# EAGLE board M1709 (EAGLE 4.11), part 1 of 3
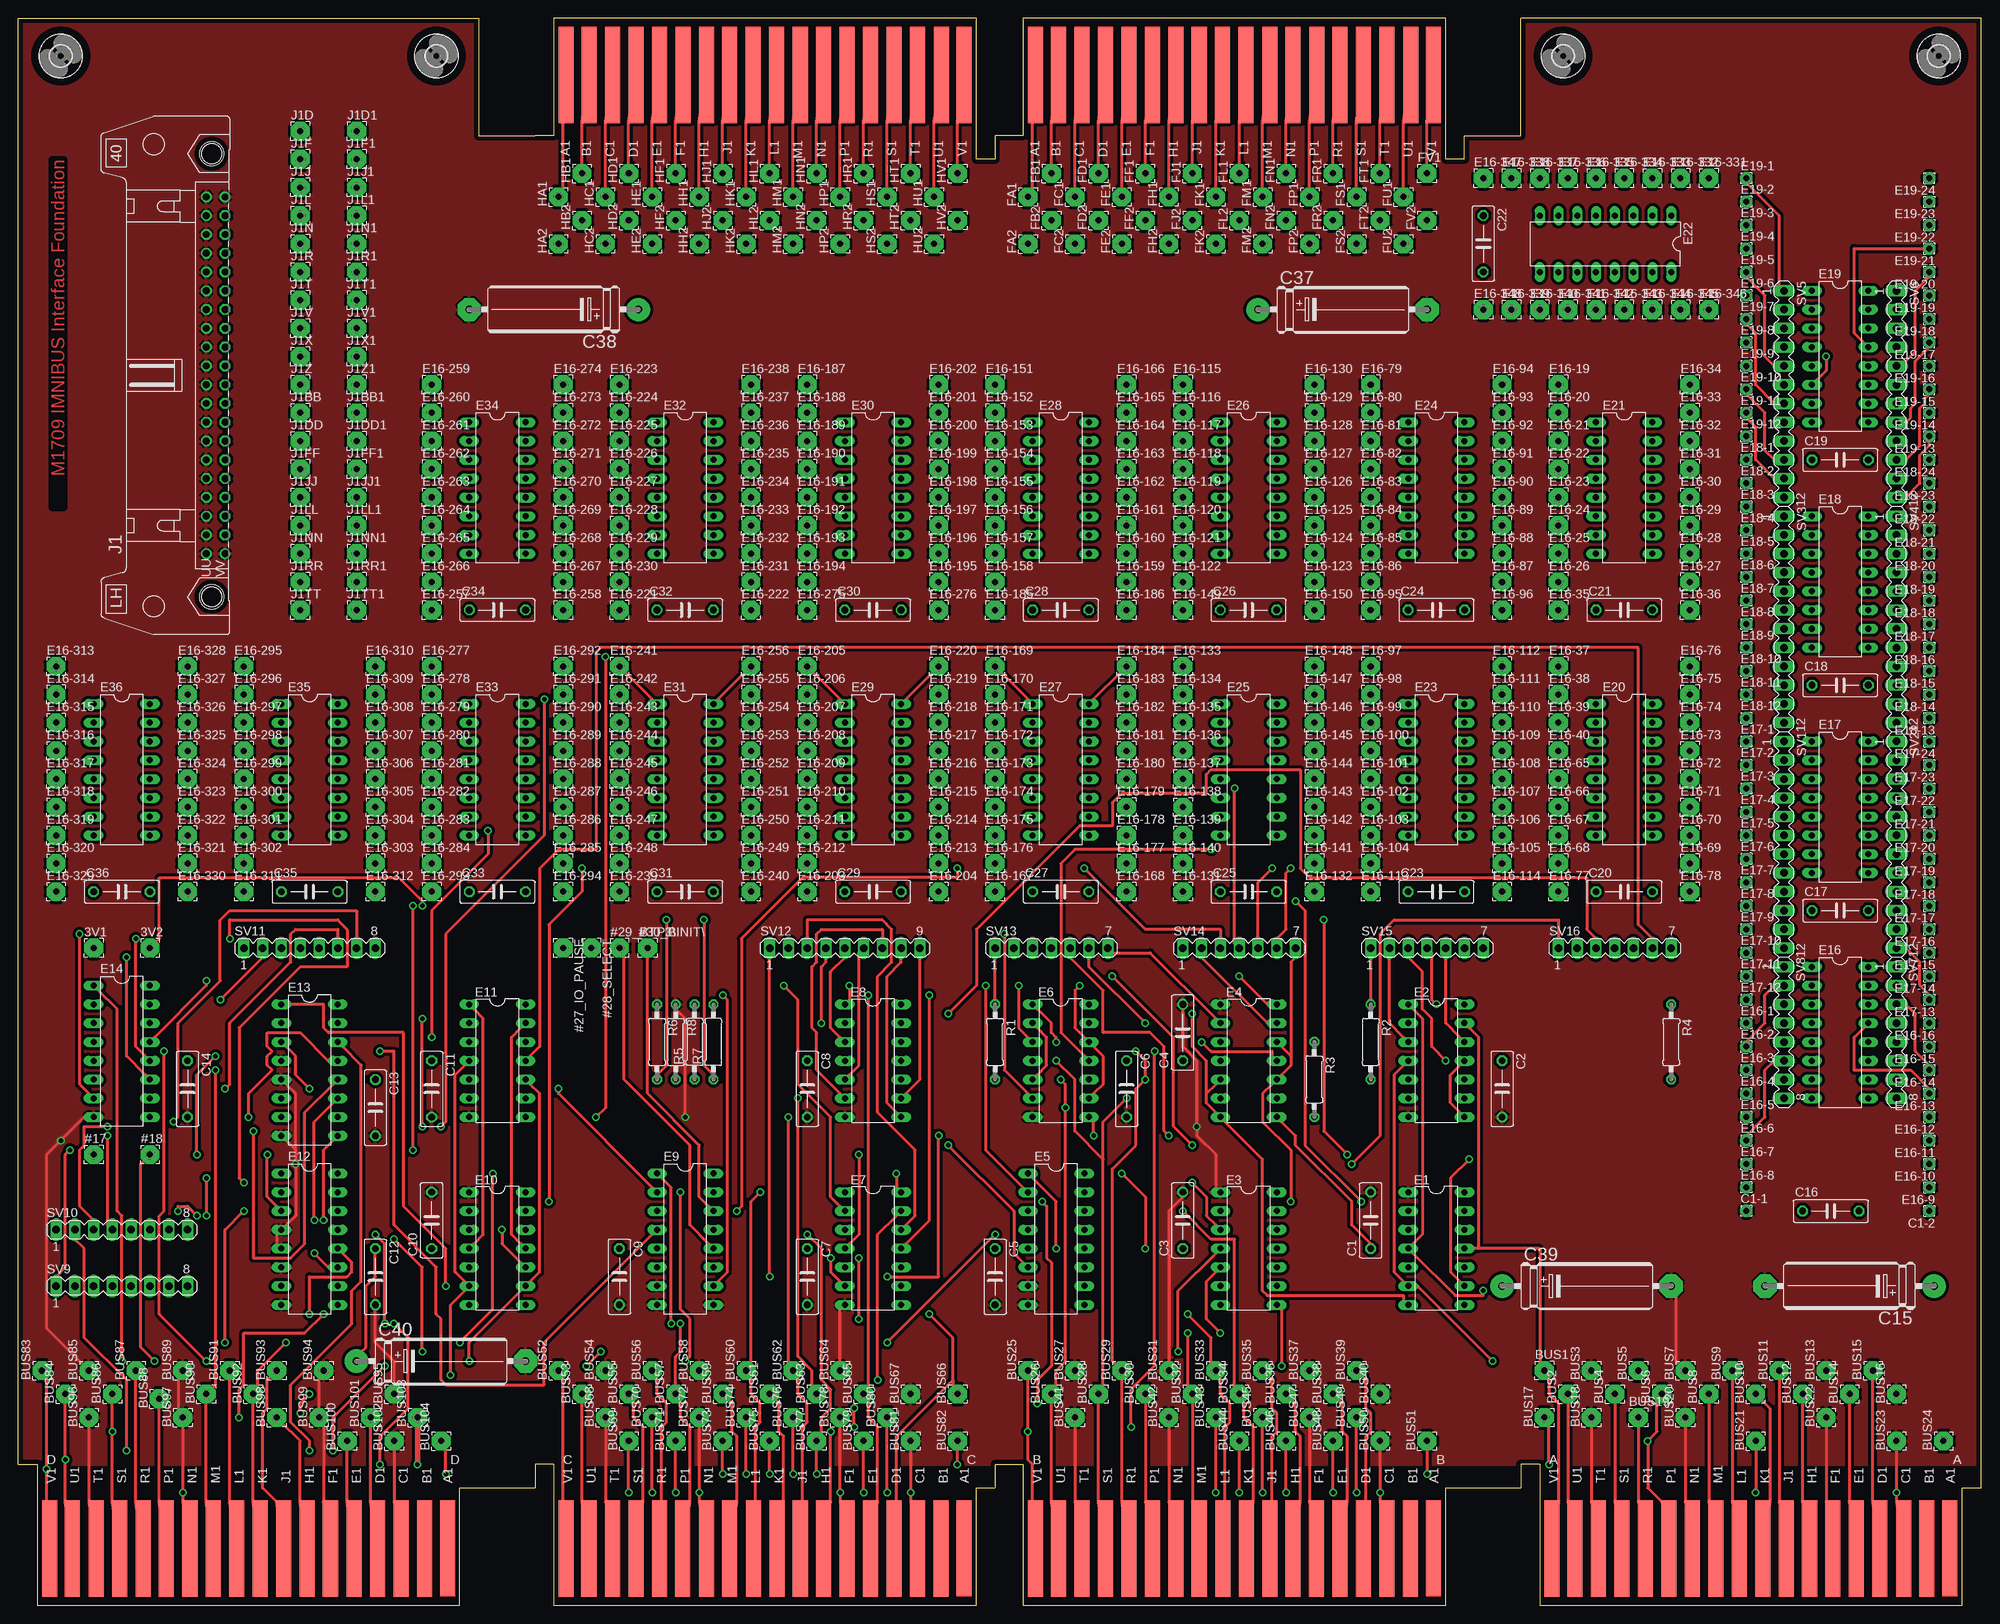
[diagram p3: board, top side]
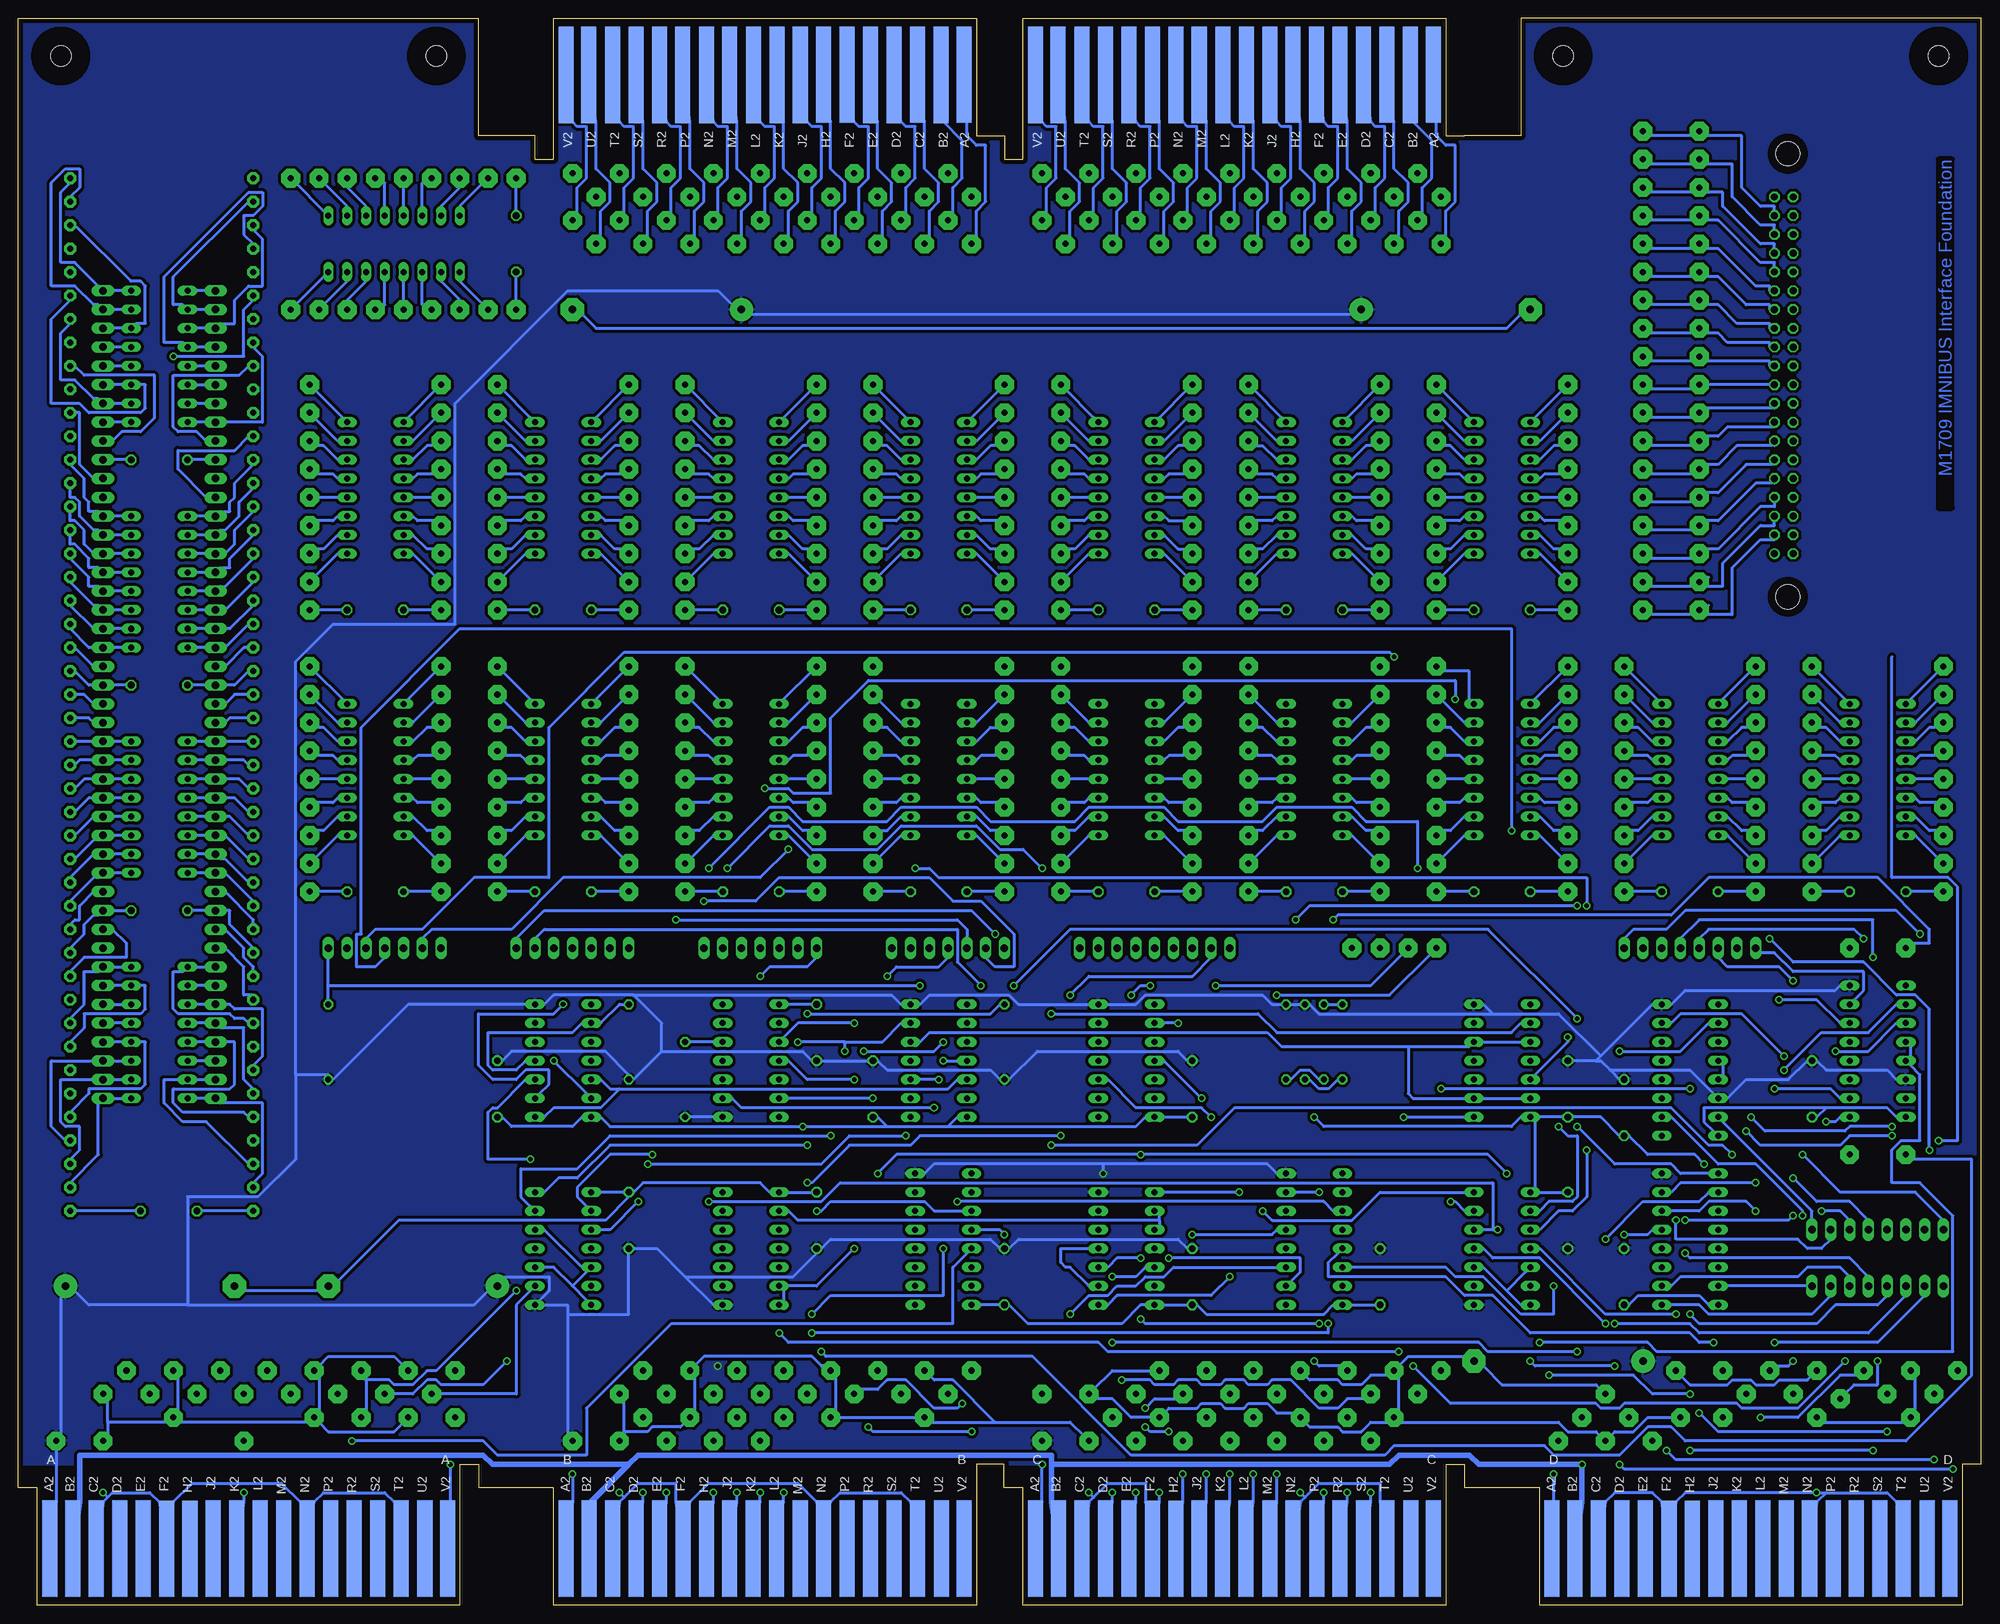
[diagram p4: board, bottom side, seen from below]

Size 265.43 x 214.63 mm. Coordinates in mm from the lower left corner, seen from the top.
Outline: 133.35,198.76 132.08,198.76 132.08,195.58
Outline: 0,19.05 0,214.63 62.23,214.63 62.23,199.39 62.23,198.76 69.85,198.76
Outline: 265.43,15.88 265.43,214.63 203.2,214.63 203.2,198.76 195.58,198.76 195.58,195.58
Copper layers (1*16): Top 0.035mm / dielectric 1.5mm / Bottom 0.035mm
Design rules "15mils": minimum track width 15mil, minimum drill 24mil, track to track 15mil, track to pad 10mil, pad to pad 10mil, via to via 10mil, smd to smd 10mil, copper to edge 25mil, drill to drill 10mil, minimum pad ring 10mil, minimum via ring 8mil, stop-mask expansion 0mil, vias tented up to drill 0mil, thermal gap 10mil
Net classes: 1 Supply: width 0.762 mm

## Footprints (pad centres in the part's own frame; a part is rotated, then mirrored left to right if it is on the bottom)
2,54/0,8 = drill 0.813 pad 2.54 octagon: 1 0,0
C075-032X103 = drill 0.914 octagon: 1 -3.81,0; 2 3.81,0
1,6/0,8 = drill 0.813 pad 1.6 octagon: 1 0,0
E22-6 = drill 1.016 pad 3.15 round: + -11.43,0 | drill 1.016 pad 3.15 octagon: - 11.43,0
DIL14 = drill 0.813 long: 1 -7.62,-3.81; 2 -5.08,-3.81; 3 -2.54,-3.81; 4 0,-3.81; 5 2.54,-3.81; 6 5.08,-3.81; 7 7.62,-3.81; 8 7.62,3.81; 9 5.08,3.81; 10 2.54,3.81; 11 0,3.81; 12 -2.54,3.81; 13 -5.08,3.81; 14 -7.62,3.81
DIL16 = drill 0.813 long: 1 -8.89,-3.81; 2 -6.35,-3.81; 3 -3.81,-3.81; 4 -1.27,-3.81; 5 1.27,-3.81; 6 3.81,-3.81; 7 6.35,-3.81; 8 8.89,-3.81; 9 8.89,3.81; 10 6.35,3.81; 11 3.81,3.81; 12 1.27,3.81; 13 -1.27,3.81; 14 -3.81,3.81; 15 -6.35,3.81; 16 -8.89,3.81
EDGE-CON2 = smd 13.017 x 2.032: A1 7.633,4.207; B1 7.639,7.327; C1 7.636,10.489; D1 7.633,13.665; E1 7.642,16.84; F1 7.642,20.041; H1 7.642,23.19; J1 7.642,26.34; K1 7.642,29.515; L1 7.642,32.69; M1 7.642,35.89; N1 7.642,39.04; P1 7.642,42.24; R1 7.642,45.39; S1 7.642,48.565; T1 7.642,51.74; U1 7.642,54.966; V1 7.642,58.026 | smd 13.017 x 2.032 bottom: A2 7.614,4.207; B2 7.642,7.328; C2 7.617,10.49; D2 7.642,13.665; E2 7.642,16.84; F2 7.617,20.041; H2 7.617,23.19; J2 7.642,26.34; K2 7.642,29.515; L2 7.642,32.69; M2 7.642,35.89; N2 7.642,39.04; P2 7.642,42.24; R2 7.642,45.39; S2 7.642,48.565; T2 7.642,51.74; U2 7.642,54.966; V2 7.642,58.026
DEC40PINH = drill 0.914 octagon: A 24.13,1.27; AA -3.81,1.27; B 24.13,-1.27; BB -3.81,-1.27; C 21.59,1.27; CC -6.35,1.27; D 21.59,-1.27; DD -6.35,-1.27; E 19.05,1.27; EE -8.89,1.27; F 19.05,-1.27; FF -8.89,-1.27; H 16.51,1.27; HH -11.43,1.27; J 16.51,-1.27; JJ -11.43,-1.27; K 13.97,1.27; KK -13.97,1.27; L 13.97,-1.27; LL -13.97,-1.27; M 11.43,1.27; MM -16.51,1.27; N 11.43,-1.27; NN -16.51,-1.27; P 8.89,1.27; PP -19.05,1.27; R 8.89,-1.27; RR -19.05,-1.27; S 6.35,1.27; SS -21.59,1.27; T 6.35,-1.27; TT -21.59,-1.27; U 3.81,1.27; UU -24.13,1.27; V 3.81,-1.27; W 1.27,1.27; X 1.27,-1.27; Y -1.27,1.27; Z -1.27,-1.27 | drill 0.914 round: VV -24.13,-1.27 | hole 3.302: -29.972,0.533; 29.972,0.533
0207/10 = drill 0.813 octagon: 1 -5.08,0; 2 5.08,0
MA12-1 = drill 1.016 long: 1 -13.97,0; 2 -11.43,0; 3 -8.89,0; 4 -6.35,0; 5 -3.81,0; 6 -1.27,0; 7 1.27,0; 8 3.81,0; 9 6.35,0; 10 8.89,0; 11 11.43,0; 12 13.97,0
MA08-1 = drill 1.016 long: 1 -8.89,0; 2 -6.35,0; 3 -3.81,0; 4 -1.27,0; 5 1.27,0; 6 3.81,0; 7 6.35,0; 8 8.89,0
MA09-1 = drill 1.016 long: 1 -10.16,0; 2 -7.62,0; 3 -5.08,0; 4 -2.54,0; 5 0,0; 6 2.54,0; 7 5.08,0; 8 7.62,0; 9 10.16,0
MA07-1 = drill 1.016 long: 1 -7.62,0; 2 -5.08,0; 3 -2.54,0; 4 0,0; 5 2.54,0; 6 5.08,0; 7 7.62,0
EDGE-CON8 = smd 2.032 x 13.017: AA1 261.223,7.709; AB1 258.118,7.684; AC1 254.956,7.684; AD1 251.765,7.684; AE1 248.59,7.693; AF1 245.389,7.668; AH1 242.24,7.668; AJ1 239.09,7.668; AK1 235.915,7.668; AL1 232.74,7.693; AM1 229.54,7.693; AN1 226.39,7.693; AP1 223.19,7.668; AR1 220.04,7.668; AS1 216.865,7.693; AT1 213.69,7.693; AU1 210.49,7.693; AV1 207.404,7.668; BA1 191.373,7.709; BB1 188.268,7.684; BC1 185.106,7.684; BD1 181.915,7.684; BE1 178.74,7.693; BF1 175.539,7.668; BH1 172.39,7.668; BJ1 169.24,7.668; BK1 166.065,7.668; BL1 162.89,7.693; BM1 159.69,7.693; BN1 156.54,7.693; BP1 153.34,7.668; BR1 150.19,7.668; BS1 147.015,7.693; BT1 143.84,7.693; BU1 140.64,7.693; BV1 137.554,7.668; CA1 127.873,7.709; CB1 124.768,7.684; CC1 121.606,7.684; CD1 118.415,7.684; CE1 115.24,7.693; CF1 112.039,7.668; CH1 108.89,7.668; CJ1 105.74,7.668; CK1 102.565,7.668; CL1 99.39,7.693; CM1 96.19,7.693; CN1 93.04,7.693; CP1 89.84,7.668; CR1 86.69,7.668; CS1 83.515,7.693; CT1 80.34,7.693; CU1 77.14,7.693; CV1 74.054,7.668; DA1 58.023,7.709; DB1 54.918,7.684; DC1 51.756,7.684; DD1 48.565,7.684; DE1 45.39,7.693; DF1 42.189,7.668; DH1 39.04,7.668; DJ1 35.89,7.668; DK1 32.715,7.668; DL1 29.54,7.693; DM1 26.34,7.693; DN1 23.19,7.693; DP1 19.99,7.668; DR1 16.84,7.668; DS1 13.665,7.693; DT1 10.49,7.693; DU1 7.29,7.693; DV1 4.204,7.668 | smd 2.032 x 13.017 bottom: AA2 261.223,7.69; AB2 258.102,7.668; AC2 254.94,7.668; AD2 251.765,7.693; AE2 248.59,7.693; AF2 245.389,7.642; AH2 242.24,7.642; AJ2 239.09,7.668; AK2 235.915,7.668; AL2 232.74,7.693; AM2 229.54,7.693; AN2 226.39,7.693; AP2 223.19,7.668; AR2 220.04,7.668; AS2 216.865,7.693; AT2 213.69,7.693; AU2 210.464,7.693; AV2 207.404,7.668; BA2 191.373,7.69; BB2 188.252,7.668; BC2 185.09,7.668; BD2 181.915,7.693; BE2 178.74,7.693; BF2 175.539,7.642; BH2 172.39,7.642; BJ2 169.24,7.668; BK2 166.065,7.668; BL2 162.89,7.693; BM2 159.69,7.693; BN2 156.54,7.693; BP2 153.34,7.668; BR2 150.19,7.668; BS2 147.015,7.693; BT2 143.84,7.693; BU2 140.614,7.693; BV2 137.554,7.668; CA2 127.873,7.69; CB2 124.752,7.668; CC2 121.59,7.668; CD2 118.415,7.693; CE2 115.24,7.693; CF2 112.039,7.642; CH2 108.89,7.642; CJ2 105.74,7.668; CK2 102.565,7.668; CL2 99.39,7.693; CM2 96.19,7.693; CN2 93.04,7.693; CP2 89.84,7.668; CR2 86.69,7.668; CS2 83.515,7.693; CT2 80.34,7.693; CU2 77.114,7.693; CV2 74.054,7.668; DA2 58.023,7.69; DB2 54.902,7.668; DC2 51.74,7.668; DD2 48.565,7.693; DE2 45.39,7.693; DF2 42.189,7.642; DH2 39.04,7.642; DJ2 35.89,7.668; DK2 32.715,7.668; DL2 29.54,7.693; DM2 26.34,7.693; DN2 23.19,7.693; DP2 19.99,7.668; DR2 16.84,7.668; DS2 13.665,7.693; DT2 10.49,7.693; DU2 7.264,7.693; DV2 4.204,7.668
2,8 = hole 2.8: 0,0

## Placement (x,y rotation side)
3V1  [2,54/0,8]  10.16,88.9 0 top
3V2  [2,54/0,8]  17.78,88.9 0 top
#17  17  [2,54/0,8]  10.16,60.96 0 top
#18  18  [2,54/0,8]  17.78,60.96 0 top
#27_IO_PAUSE  27  [2,54/0,8]  73.66,88.9 270 top
#28_SELECT  28  [2,54/0,8]  77.47,88.9 270 top
#29_BTP3\  29  [2,54/0,8]  81.28,88.9 0 top
#30_BINIT\  30  [2,54/0,8]  85.09,88.9 0 top
BUS1  [2,54/0,8]  206.38,31.75 0 top
BUS2  [2,54/0,8]  209.55,28.58 90 top
BUS3  [2,54/0,8]  212.72,31.75 90 top
BUS4  [2,54/0,8]  215.9,28.58 90 top
BUS5  [2,54/0,8]  219.07,31.75 90 top
BUS6  [2,54/0,8]  222.25,28.58 90 top
BUS7  [2,54/0,8]  225.43,31.75 90 top
BUS8  [2,54/0,8]  228.6,28.58 90 top
BUS9  [2,54/0,8]  231.78,31.75 90 top
BUS10  [2,54/0,8]  234.95,28.58 90 top
BUS11  [2,54/0,8]  238.12,31.75 90 top
BUS12  [2,54/0,8]  241.3,28.58 90 top
BUS13  [2,54/0,8]  244.47,31.75 90 top
BUS14  [2,54/0,8]  247.65,28.58 90 top
BUS15  [2,54/0,8]  250.82,31.75 90 top
BUS16  [2,54/0,8]  254,28.58 90 top
BUS17  [2,54/0,8]  206.38,25.4 90 top
BUS18  [2,54/0,8]  212.72,25.4 90 top
BUS19  [2,54/0,8]  219.07,25.4 0 top
BUS20  [2,54/0,8]  225.43,25.4 90 top
BUS21  [2,54/0,8]  234.95,22.23 90 top
BUS22  [2,54/0,8]  244.47,25.4 90 top
BUS23  [2,54/0,8]  254,22.23 90 top
BUS24  [2,54/0,8]  260.35,22.23 90 top
BUS25  [2,54/0,8]  136.53,31.75 90 top
BUS26  [2,54/0,8]  139.7,28.58 90 top
BUS27  [2,54/0,8]  142.88,31.75 90 top
BUS28  [2,54/0,8]  146.05,28.58 90 top
BUS29  [2,54/0,8]  149.22,31.75 90 top
BUS30  [2,54/0,8]  152.4,28.58 90 top
BUS31  [2,54/0,8]  155.57,31.75 90 top
BUS32  [2,54/0,8]  158.75,28.58 90 top
BUS33  [2,54/0,8]  161.93,31.75 90 top
BUS34  [2,54/0,8]  165.1,28.58 90 top
BUS35  [2,54/0,8]  168.28,31.75 90 top
BUS36  [2,54/0,8]  171.45,28.58 90 top
BUS37  [2,54/0,8]  174.62,31.75 90 top
BUS38  [2,54/0,8]  177.8,28.58 90 top
BUS39  [2,54/0,8]  180.97,31.75 90 top
BUS40  [2,54/0,8]  184.15,28.58 90 top
BUS41  [2,54/0,8]  142.88,25.4 90 top
BUS42  [2,54/0,8]  155.57,25.4 90 top
BUS43  [2,54/0,8]  161.93,25.4 90 top
BUS44  [2,54/0,8]  165.1,22.23 90 top
BUS45  [2,54/0,8]  168.28,25.4 90 top
BUS46  [2,54/0,8]  171.45,22.23 90 top
BUS47  [2,54/0,8]  174.62,25.4 90 top
BUS48  [2,54/0,8]  177.8,22.23 90 top
BUS49  [2,54/0,8]  180.97,25.4 90 top
BUS50  [2,54/0,8]  184.15,22.23 90 top
BUS51  [2,54/0,8]  190.5,22.23 90 top
BUS52  [2,54/0,8]  73.03,31.75 90 top
BUS53  [2,54/0,8]  76.2,28.58 90 top
BUS54  [2,54/0,8]  79.38,31.75 90 top
BUS55  [2,54/0,8]  82.55,28.58 90 top
BUS56  [2,54/0,8]  85.72,31.75 90 top
BUS57  [2,54/0,8]  88.9,28.58 90 top
BUS58  [2,54/0,8]  92.08,31.75 90 top
BUS59  [2,54/0,8]  95.25,28.58 90 top
BUS60  [2,54/0,8]  98.42,31.75 90 top
BUS61  [2,54/0,8]  101.6,28.58 90 top
BUS62  [2,54/0,8]  104.78,31.75 90 top
BUS63  [2,54/0,8]  107.95,28.58 90 top
BUS64  [2,54/0,8]  111.12,31.75 90 top
BUS65  [2,54/0,8]  114.3,28.58 90 top
BUS66  [2,54/0,8]  127,28.58 90 top
BUS67  [2,54/0,8]  120.65,28.58 90 top
BUS68  [2,54/0,8]  79.38,25.4 90 top
BUS69  [2,54/0,8]  82.55,22.23 90 top
BUS70  [2,54/0,8]  85.72,25.4 90 top
BUS71  [2,54/0,8]  88.9,22.23 90 top
BUS72  [2,54/0,8]  92.08,25.4 90 top
BUS73  [2,54/0,8]  95.25,22.23 90 top
BUS74  [2,54/0,8]  98.42,25.4 90 top
BUS75  [2,54/0,8]  101.6,22.23 90 top
BUS76  [2,54/0,8]  104.78,25.4 90 top
BUS77  [2,54/0,8]  107.95,22.23 90 top
BUS78  [2,54/0,8]  111.12,25.4 90 top
BUS79  [2,54/0,8]  114.3,22.23 90 top
BUS80  [2,54/0,8]  117.47,25.4 90 top
BUS81  [2,54/0,8]  120.65,22.23 90 top
BUS82  [2,54/0,8]  127,22.23 90 top
BUS83  [2,54/0,8]  3.17,31.75 90 top
BUS84  [2,54/0,8]  6.35,28.58 90 top
BUS85  [2,54/0,8]  9.53,31.75 90 top
BUS86  [2,54/0,8]  12.7,28.58 90 top
BUS87  [2,54/0,8]  15.88,31.75 90 top
BUS88  [2,54/0,8]  19.05,27.94 90 top
BUS89  [2,54/0,8]  22.23,31.75 90 top
BUS90  [2,54/0,8]  25.4,28.58 90 top
BUS91  [2,54/0,8]  28.57,31.75 90 top
BUS92  [2,54/0,8]  31.75,28.58 90 top
BUS93  [2,54/0,8]  34.92,31.75 90 top
BUS94  [2,54/0,8]  41.27,31.75 90 top
BUS95  [2,54/0,8]  50.8,28.58 90 top
BUS96  [2,54/0,8]  9.53,25.4 90 top
BUS97  [2,54/0,8]  22.23,25.4 90 top
BUS98  [2,54/0,8]  34.92,25.4 90 top
BUS99  [2,54/0,8]  40.64,25.4 90 top
BUS100  [2,54/0,8]  44.45,22.23 90 top
BUS101  [2,54/0,8]  47.62,25.4 90 top
BUS102  [2,54/0,8]  50.8,22.23 90 top
BUS103  [2,54/0,8]  53.98,25.4 90 top
BUS104  [2,54/0,8]  57.15,22.23 90 top
C1  [C075-032X103]  182.88,52.07 90 top
C1-1  [1,6/0,8]  233.68,53.34 0 top
C1-2  [1,6/0,8]  258.44,53.34 180 top
C2  [C075-032X103]  200.66,69.85 270 top
C3  [C075-032X103]  157.48,52.07 90 top
C4  [C075-032X103]  157.48,77.47 90 top
C5  [C075-032X103]  132.08,44.45 270 top
C6  [C075-032X103]  149.86,69.85 270 top
C7  [C075-032X103]  106.68,44.45 270 top
C8  [C075-032X103]  106.68,69.85 270 top
C9  [C075-032X103]  81.28,44.45 270 top
C10  [C075-032X103]  55.88,52.07 90 top
C11  [C075-032X103]  55.88,69.85 270 top
C12  [C075-032X103]  48.26,44.45 270 top
C13  [C075-032X103]  48.26,67.31 270 top
C14  [C075-032X103]  22.86,69.85 270 top
C15  [E22-6]  247.65,43.18 180 top
C16  [C075-032X103]  245.11,53.34 0 top
C17  [C075-032X103]  246.38,93.98 0 top
C18  [C075-032X103]  246.38,124.46 0 top
C19  [C075-032X103]  246.38,154.94 0 top
C20  [C075-032X103]  217.17,96.52 0 top
C21  [C075-032X103]  217.17,134.62 0 top
C22  [C075-032X103]  198.12,184.15 270 top
C23  [C075-032X103]  191.77,96.52 0 top
C24  [C075-032X103]  191.77,134.62 0 top
C25  [C075-032X103]  166.37,96.52 0 top
C26  [C075-032X103]  166.37,134.62 0 top
C27  [C075-032X103]  140.97,96.52 0 top
C28  [C075-032X103]  140.97,134.62 0 top
C29  [C075-032X103]  115.57,96.52 0 top
C30  [C075-032X103]  115.57,134.62 0 top
C31  [C075-032X103]  90.17,96.52 0 top
C32  [C075-032X103]  90.17,134.62 0 top
C33  [C075-032X103]  64.77,96.52 0 top
C34  [C075-032X103]  64.77,134.62 0 top
C35  [C075-032X103]  39.37,96.52 0 top
C36  [C075-032X103]  13.97,96.52 0 top
C37  [E22-6]  179.07,175.26 0 top
C38  [E22-6]  72.39,175.26 180 top
C39  [E22-6]  212.09,43.18 0 top
C40  [E22-6]  57.15,33.02 0 top
E1  SP380N  [DIL14]  191.77,48.26 270 top
E2  DEC8881  [DIL14]  191.77,73.66 270 top
E3  SP380N  [DIL14]  166.37,48.26 270 top
E4  SP380N  [DIL14]  166.37,73.66 270 top
E5  DS8837N  [DIL16]  140.34,49.53 270 top
E6  DEC8881  [DIL14]  140.97,73.66 270 top
E7  DEC8881  [DIL14]  115.57,48.26 270 top
E8  DEC8881  [DIL14]  115.57,73.66 270 top
E9  DS8837N  [DIL16]  90.17,49.53 270 top
E10  SP380N  [DIL14]  64.77,48.26 270 top
E11  DEC8881  [DIL14]  64.77,73.66 270 top
E12  74LS138N  [DIL16]  39.37,49.53 270 top
E13  74LS138N  [DIL16]  39.37,72.39 270 top
E14  74LS138N  [DIL16]  13.97,74.93 270 top
E16  [DIL16]  246.38,77.47 270 top
E16-1  [1,6/0,8]  233.68,78.74 0 top
E16-2  [1,6/0,8]  233.68,75.57 0 top
E16-3  [1,6/0,8]  233.68,72.39 0 top
E16-4  [1,6/0,8]  233.68,69.22 0 top
E16-5  [1,6/0,8]  233.68,66.04 0 top
E16-6  [1,6/0,8]  233.68,62.87 0 top
E16-7  [1,6/0,8]  233.68,59.69 0 top
E16-8  [1,6/0,8]  233.68,56.52 0 top
E16-9  [1,6/0,8]  258.44,56.52 180 top
E16-10  [1,6/0,8]  258.44,59.69 180 top
E16-11  [1,6/0,8]  258.44,62.87 180 top
E16-12  [1,6/0,8]  258.44,66.04 180 top
E16-13  [1,6/0,8]  258.44,69.22 180 top
E16-14  [1,6/0,8]  258.44,72.39 180 top
E16-15  [1,6/0,8]  258.44,75.57 180 top
E16-16  [1,6/0,8]  258.44,78.74 180 top
E16-19  [2,54/0,8]  208.28,165.1 0 top
E16-20  [2,54/0,8]  208.28,161.29 0 top
E16-21  [2,54/0,8]  208.28,157.48 0 top
E16-22  [2,54/0,8]  208.28,153.67 0 top
E16-23  [2,54/0,8]  208.28,149.86 0 top
E16-24  [2,54/0,8]  208.28,146.05 0 top
E16-25  [2,54/0,8]  208.28,142.24 0 top
E16-26  [2,54/0,8]  208.28,138.43 0 top
E16-27  [2,54/0,8]  226.06,138.43 0 top
E16-28  [2,54/0,8]  226.06,142.24 0 top
E16-29  [2,54/0,8]  226.06,146.05 0 top
E16-30  [2,54/0,8]  226.06,149.86 0 top
E16-31  [2,54/0,8]  226.06,153.67 0 top
E16-32  [2,54/0,8]  226.06,157.48 0 top
E16-33  [2,54/0,8]  226.06,161.29 0 top
E16-34  [2,54/0,8]  226.06,165.1 0 top
E16-35  [2,54/0,8]  208.28,134.62 0 top
E16-36  [2,54/0,8]  226.06,134.62 0 top
E16-37  [2,54/0,8]  208.28,127 0 top
E16-38  [2,54/0,8]  208.28,123.19 0 top
E16-39  [2,54/0,8]  208.28,119.38 0 top
E16-40  [2,54/0,8]  208.28,115.57 0 top
E16-65  [2,54/0,8]  208.28,111.76 0 top
E16-66  [2,54/0,8]  208.28,107.95 0 top
E16-67  [2,54/0,8]  208.28,104.14 0 top
E16-68  [2,54/0,8]  208.28,100.33 0 top
E16-69  [2,54/0,8]  226.06,100.33 0 top
E16-70  [2,54/0,8]  226.06,104.14 0 top
E16-71  [2,54/0,8]  226.06,107.95 0 top
E16-72  [2,54/0,8]  226.06,111.76 0 top
E16-73  [2,54/0,8]  226.06,115.57 0 top
E16-74  [2,54/0,8]  226.06,119.38 0 top
E16-75  [2,54/0,8]  226.06,123.19 0 top
E16-76  [2,54/0,8]  226.06,127 0 top
E16-77  [2,54/0,8]  208.28,96.52 0 top
E16-78  [2,54/0,8]  226.06,96.52 0 top
E16-79  [2,54/0,8]  182.88,165.1 0 top
E16-80  [2,54/0,8]  182.88,161.29 0 top
E16-81  [2,54/0,8]  182.88,157.48 0 top
E16-82  [2,54/0,8]  182.88,153.67 0 top
E16-83  [2,54/0,8]  182.88,149.86 0 top
E16-84  [2,54/0,8]  182.88,146.05 0 top
E16-85  [2,54/0,8]  182.88,142.24 0 top
E16-86  [2,54/0,8]  182.88,138.43 0 top
E16-87  [2,54/0,8]  200.66,138.43 0 top
E16-88  [2,54/0,8]  200.66,142.24 0 top
E16-89  [2,54/0,8]  200.66,146.05 0 top
E16-90  [2,54/0,8]  200.66,149.86 0 top
E16-91  [2,54/0,8]  200.66,153.67 0 top
E16-92  [2,54/0,8]  200.66,157.48 0 top
E16-93  [2,54/0,8]  200.66,161.29 0 top
E16-94  [2,54/0,8]  200.66,165.1 0 top
E16-95  [2,54/0,8]  182.88,134.62 0 top
E16-96  [2,54/0,8]  200.66,134.62 0 top
E16-97  [2,54/0,8]  182.88,127 0 top
E16-98  [2,54/0,8]  182.88,123.19 0 top
E16-99  [2,54/0,8]  182.88,119.38 0 top
E16-100  [2,54/0,8]  182.88,115.57 0 top
E16-101  [2,54/0,8]  182.88,111.76 0 top
E16-102  [2,54/0,8]  182.88,107.95 0 top
E16-103  [2,54/0,8]  182.88,104.14 0 top
E16-104  [2,54/0,8]  182.88,100.33 0 top
E16-105  [2,54/0,8]  200.66,100.33 0 top
E16-106  [2,54/0,8]  200.66,104.14 0 top
E16-107  [2,54/0,8]  200.66,107.95 0 top
E16-108  [2,54/0,8]  200.66,111.76 0 top
E16-109  [2,54/0,8]  200.66,115.57 0 top
E16-110  [2,54/0,8]  200.66,119.38 0 top
E16-111  [2,54/0,8]  200.66,123.19 0 top
E16-112  [2,54/0,8]  200.66,127 0 top
E16-113  [2,54/0,8]  182.88,96.52 0 top
E16-114  [2,54/0,8]  200.66,96.52 0 top
E16-115  [2,54/0,8]  157.48,165.1 0 top
E16-116  [2,54/0,8]  157.48,161.29 0 top
E16-117  [2,54/0,8]  157.48,157.48 0 top
E16-118  [2,54/0,8]  157.48,153.67 0 top
E16-119  [2,54/0,8]  157.48,149.86 0 top
E16-120  [2,54/0,8]  157.48,146.05 0 top
E16-121  [2,54/0,8]  157.48,142.24 0 top
E16-122  [2,54/0,8]  157.48,138.43 0 top
E16-123  [2,54/0,8]  175.26,138.43 0 top
E16-124  [2,54/0,8]  175.26,142.24 0 top
E16-125  [2,54/0,8]  175.26,146.05 0 top
E16-126  [2,54/0,8]  175.26,149.86 0 top
E16-127  [2,54/0,8]  175.26,153.67 0 top
E16-128  [2,54/0,8]  175.26,157.48 0 top
E16-129  [2,54/0,8]  175.26,161.29 0 top
E16-130  [2,54/0,8]  175.26,165.1 0 top
E16-131  [2,54/0,8]  157.48,96.52 0 top
E16-132  [2,54/0,8]  175.26,96.52 0 top
E16-133  [2,54/0,8]  157.48,127 0 top
E16-134  [2,54/0,8]  157.48,123.19 0 top
E16-135  [2,54/0,8]  157.48,119.38 0 top
E16-136  [2,54/0,8]  157.48,115.57 0 top
E16-137  [2,54/0,8]  157.48,111.76 0 top
E16-138  [2,54/0,8]  157.48,107.95 0 top
E16-139  [2,54/0,8]  157.48,104.14 0 top
E16-140  [2,54/0,8]  157.48,100.33 0 top
E16-141  [2,54/0,8]  175.26,100.33 0 top
E16-142  [2,54/0,8]  175.26,104.14 0 top
E16-143  [2,54/0,8]  175.26,107.95 0 top
E16-144  [2,54/0,8]  175.26,111.76 0 top
E16-145  [2,54/0,8]  175.26,115.57 0 top
E16-146  [2,54/0,8]  175.26,119.38 0 top
E16-147  [2,54/0,8]  175.26,123.19 0 top
E16-148  [2,54/0,8]  175.26,127 0 top
E16-149  [2,54/0,8]  157.48,134.62 0 top
E16-150  [2,54/0,8]  175.26,134.62 0 top
E16-151  [2,54/0,8]  132.08,165.1 0 top
E16-152  [2,54/0,8]  132.08,161.29 0 top
E16-153  [2,54/0,8]  132.08,157.48 0 top
E16-154  [2,54/0,8]  132.08,153.67 0 top
E16-155  [2,54/0,8]  132.08,149.86 0 top
E16-156  [2,54/0,8]  132.08,146.05 0 top
E16-157  [2,54/0,8]  132.08,142.24 0 top
E16-158  [2,54/0,8]  132.08,138.43 0 top
E16-159  [2,54/0,8]  149.86,138.43 0 top
E16-160  [2,54/0,8]  149.86,142.24 0 top
E16-161  [2,54/0,8]  149.86,146.05 0 top
E16-162  [2,54/0,8]  149.86,149.86 0 top
E16-163  [2,54/0,8]  149.86,153.67 0 top
E16-164  [2,54/0,8]  149.86,157.48 0 top
E16-165  [2,54/0,8]  149.86,161.29 0 top
E16-166  [2,54/0,8]  149.86,165.1 0 top
E16-167  [2,54/0,8]  132.08,96.52 0 top
E16-168  [2,54/0,8]  149.86,96.52 0 top
E16-169  [2,54/0,8]  132.08,127 0 top
E16-170  [2,54/0,8]  132.08,123.19 0 top
E16-171  [2,54/0,8]  132.08,119.38 0 top
E16-172  [2,54/0,8]  132.08,115.57 0 top
E16-173  [2,54/0,8]  132.08,111.76 0 top
E16-174  [2,54/0,8]  132.08,107.95 0 top
E16-175  [2,54/0,8]  132.08,104.14 0 top
E16-176  [2,54/0,8]  132.08,100.33 0 top
E16-177  [2,54/0,8]  149.86,100.33 0 top
E16-178  [2,54/0,8]  149.86,104.14 0 top
E16-179  [2,54/0,8]  149.86,107.95 0 top
E16-180  [2,54/0,8]  149.86,111.76 0 top
E16-181  [2,54/0,8]  149.86,115.57 0 top
E16-182  [2,54/0,8]  149.86,119.38 0 top
E16-183  [2,54/0,8]  149.86,123.19 0 top
E16-184  [2,54/0,8]  149.86,127 0 top
E16-185  [2,54/0,8]  132.08,134.62 0 top
E16-186  [2,54/0,8]  149.86,134.62 0 top
E16-187  [2,54/0,8]  106.68,165.1 0 top
E16-188  [2,54/0,8]  106.68,161.29 0 top
E16-189  [2,54/0,8]  106.68,157.48 0 top
E16-190  [2,54/0,8]  106.68,153.67 0 top
E16-191  [2,54/0,8]  106.68,149.86 0 top
E16-192  [2,54/0,8]  106.68,146.05 0 top
E16-193  [2,54/0,8]  106.68,142.24 0 top
E16-194  [2,54/0,8]  106.68,138.43 0 top
E16-195  [2,54/0,8]  124.46,138.43 0 top
E16-196  [2,54/0,8]  124.46,142.24 0 top
E16-197  [2,54/0,8]  124.46,146.05 0 top
E16-198  [2,54/0,8]  124.46,149.86 0 top
E16-199  [2,54/0,8]  124.46,153.67 0 top
E16-200  [2,54/0,8]  124.46,157.48 0 top
E16-201  [2,54/0,8]  124.46,161.29 0 top
E16-202  [2,54/0,8]  124.46,165.1 0 top
E16-203  [2,54/0,8]  106.68,96.52 0 top
E16-204  [2,54/0,8]  124.46,96.52 0 top
E16-205  [2,54/0,8]  106.68,127 0 top
E16-206  [2,54/0,8]  106.68,123.19 0 top
E16-207  [2,54/0,8]  106.68,119.38 0 top
E16-208  [2,54/0,8]  106.68,115.57 0 top
E16-209  [2,54/0,8]  106.68,111.76 0 top
E16-210  [2,54/0,8]  106.68,107.95 0 top
E16-211  [2,54/0,8]  106.68,104.14 0 top
E16-212  [2,54/0,8]  106.68,100.33 0 top
E16-213  [2,54/0,8]  124.46,100.33 0 top
E16-214  [2,54/0,8]  124.46,104.14 0 top
E16-215  [2,54/0,8]  124.46,107.95 0 top
E16-216  [2,54/0,8]  124.46,111.76 0 top
E16-217  [2,54/0,8]  124.46,115.57 0 top
E16-218  [2,54/0,8]  124.46,119.38 0 top
E16-219  [2,54/0,8]  124.46,123.19 0 top
E16-220  [2,54/0,8]  124.46,127 0 top
E16-221  [2,54/0,8]  81.28,134.62 0 top
E16-222  [2,54/0,8]  99.06,134.62 0 top
E16-223  [2,54/0,8]  81.28,165.1 0 top
E16-224  [2,54/0,8]  81.28,161.29 0 top
E16-225  [2,54/0,8]  81.28,157.48 0 top
E16-226  [2,54/0,8]  81.28,153.67 0 top
E16-227  [2,54/0,8]  81.28,149.86 0 top
E16-228  [2,54/0,8]  81.28,146.05 0 top
E16-229  [2,54/0,8]  81.28,142.24 0 top
E16-230  [2,54/0,8]  81.28,138.43 0 top
E16-231  [2,54/0,8]  99.06,138.43 0 top
E16-232  [2,54/0,8]  99.06,142.24 0 top
E16-233  [2,54/0,8]  99.06,146.05 0 top
E16-234  [2,54/0,8]  99.06,149.86 0 top
E16-235  [2,54/0,8]  99.06,153.67 0 top
E16-236  [2,54/0,8]  99.06,157.48 0 top
E16-237  [2,54/0,8]  99.06,161.29 0 top
E16-238  [2,54/0,8]  99.06,165.1 0 top
E16-239  [2,54/0,8]  81.28,96.52 0 top
E16-240  [2,54/0,8]  99.06,96.52 0 top
E16-241  [2,54/0,8]  81.28,127 0 top
E16-242  [2,54/0,8]  81.28,123.19 0 top
E16-243  [2,54/0,8]  81.28,119.38 0 top
E16-244  [2,54/0,8]  81.28,115.57 0 top
E16-245  [2,54/0,8]  81.28,111.76 0 top
E16-246  [2,54/0,8]  81.28,107.95 0 top
E16-247  [2,54/0,8]  81.28,104.14 0 top
E16-248  [2,54/0,8]  81.28,100.33 0 top
E16-249  [2,54/0,8]  99.06,100.33 0 top
E16-250  [2,54/0,8]  99.06,104.14 0 top
E16-251  [2,54/0,8]  99.06,107.95 0 top
E16-252  [2,54/0,8]  99.06,111.76 0 top
E16-253  [2,54/0,8]  99.06,115.57 0 top
E16-254  [2,54/0,8]  99.06,119.38 0 top
E16-255  [2,54/0,8]  99.06,123.19 0 top
E16-256  [2,54/0,8]  99.06,127 0 top
E16-257  [2,54/0,8]  55.88,134.62 0 top
E16-258  [2,54/0,8]  73.66,134.62 0 top
E16-259  [2,54/0,8]  55.88,165.1 0 top
E16-260  [2,54/0,8]  55.88,161.29 0 top
E16-261  [2,54/0,8]  55.88,157.48 0 top
E16-262  [2,54/0,8]  55.88,153.67 0 top
E16-263  [2,54/0,8]  55.88,149.86 0 top
E16-264  [2,54/0,8]  55.88,146.05 0 top
E16-265  [2,54/0,8]  55.88,142.24 0 top
E16-266  [2,54/0,8]  55.88,138.43 0 top
E16-267  [2,54/0,8]  73.66,138.43 0 top
E16-268  [2,54/0,8]  73.66,142.24 0 top
E16-269  [2,54/0,8]  73.66,146.05 0 top
E16-270  [2,54/0,8]  73.66,149.86 0 top
E16-271  [2,54/0,8]  73.66,153.67 0 top
E16-272  [2,54/0,8]  73.66,157.48 0 top
E16-273  [2,54/0,8]  73.66,161.29 0 top
E16-274  [2,54/0,8]  73.66,165.1 0 top
E16-275  [2,54/0,8]  106.68,134.62 0 top
E16-276  [2,54/0,8]  124.46,134.62 0 top
E16-277  [2,54/0,8]  55.88,127 0 top
E16-278  [2,54/0,8]  55.88,123.19 0 top
E16-279  [2,54/0,8]  55.88,119.38 0 top
E16-280  [2,54/0,8]  55.88,115.57 0 top
E16-281  [2,54/0,8]  55.88,111.76 0 top
E16-282  [2,54/0,8]  55.88,107.95 0 top
E16-283  [2,54/0,8]  55.88,104.14 0 top
E16-284  [2,54/0,8]  55.88,100.33 0 top
E16-285  [2,54/0,8]  73.66,100.33 0 top
E16-286  [2,54/0,8]  73.66,104.14 0 top
E16-287  [2,54/0,8]  73.66,107.95 0 top
E16-288  [2,54/0,8]  73.66,111.76 0 top
E16-289  [2,54/0,8]  73.66,115.57 0 top
E16-290  [2,54/0,8]  73.66,119.38 0 top
E16-291  [2,54/0,8]  73.66,123.19 0 top
E16-292  [2,54/0,8]  73.66,127 0 top
E16-293  [2,54/0,8]  55.88,96.52 0 top
E16-294  [2,54/0,8]  73.66,96.52 0 top
E16-295  [2,54/0,8]  30.48,127 0 top
E16-296  [2,54/0,8]  30.48,123.19 0 top
E16-297  [2,54/0,8]  30.48,119.38 0 top
E16-298  [2,54/0,8]  30.48,115.57 0 top
E16-299  [2,54/0,8]  30.48,111.76 0 top
E16-300  [2,54/0,8]  30.48,107.95 0 top
E16-301  [2,54/0,8]  30.48,104.14 0 top
E16-302  [2,54/0,8]  30.48,100.33 0 top
E16-303  [2,54/0,8]  48.26,100.33 0 top
E16-304  [2,54/0,8]  48.26,104.14 0 top
E16-305  [2,54/0,8]  48.26,107.95 0 top
E16-306  [2,54/0,8]  48.26,111.76 0 top
E16-307  [2,54/0,8]  48.26,115.57 0 top
E16-308  [2,54/0,8]  48.26,119.38 0 top
E16-309  [2,54/0,8]  48.26,123.19 0 top
E16-310  [2,54/0,8]  48.26,127 0 top
E16-311  [2,54/0,8]  30.48,96.52 0 top
E16-312  [2,54/0,8]  48.26,96.52 0 top
E16-313  [2,54/0,8]  5.08,127 0 top
E16-314  [2,54/0,8]  5.08,123.19 0 top
E16-315  [2,54/0,8]  5.08,119.38 0 top
E16-316  [2,54/0,8]  5.08,115.57 0 top
E16-317  [2,54/0,8]  5.08,111.76 0 top
E16-318  [2,54/0,8]  5.08,107.95 0 top
E16-319  [2,54/0,8]  5.08,104.14 0 top
E16-320  [2,54/0,8]  5.08,100.33 0 top
E16-321  [2,54/0,8]  22.86,100.33 0 top
E16-322  [2,54/0,8]  22.86,104.14 0 top
E16-323  [2,54/0,8]  22.86,107.95 0 top
E16-324  [2,54/0,8]  22.86,111.76 0 top
E16-325  [2,54/0,8]  22.86,115.57 0 top
E16-326  [2,54/0,8]  22.86,119.38 0 top
E16-327  [2,54/0,8]  22.86,123.19 0 top
E16-328  [2,54/0,8]  22.86,127 0 top
E16-329  [2,54/0,8]  5.08,96.52 0 top
E16-330  [2,54/0,8]  22.86,96.52 0 top
E16-331  [2,54/0,8]  228.6,193.04 0 top
E16-332  [2,54/0,8]  224.79,193.04 0 top
E16-333  [2,54/0,8]  220.98,193.04 0 top
E16-334  [2,54/0,8]  217.17,193.04 0 top
E16-335  [2,54/0,8]  213.36,193.04 0 top
E16-336  [2,54/0,8]  209.55,193.04 0 top
E16-337  [2,54/0,8]  205.74,193.04 0 top
E16-338  [2,54/0,8]  201.93,193.04 0 top
E16-339  [2,54/0,8]  201.93,175.26 0 top
E16-340  [2,54/0,8]  205.74,175.26 0 top
E16-341  [2,54/0,8]  209.55,175.26 0 top
E16-342  [2,54/0,8]  213.36,175.26 0 top
E16-343  [2,54/0,8]  217.17,175.26 0 top
E16-344  [2,54/0,8]  220.98,175.26 0 top
E16-345  [2,54/0,8]  224.79,175.26 0 top
E16-346  [2,54/0,8]  228.6,175.26 0 top
E16-347  [2,54/0,8]  198.12,193.04 0 top
E16-348  [2,54/0,8]  198.12,175.26 0 top
E17  [DIL16]  246.38,107.95 270 top
E17-1  [1,6/0,8]  233.68,116.84 0 top
E17-2  [1,6/0,8]  233.68,113.67 0 top
E17-3  [1,6/0,8]  233.68,110.49 0 top
E17-4  [1,6/0,8]  233.68,107.32 0 top
E17-5  [1,6/0,8]  233.68,104.14 0 top
E17-6  [1,6/0,8]  233.68,100.97 0 top
E17-7  [1,6/0,8]  233.68,97.79 0 top
E17-8  [1,6/0,8]  233.68,94.62 0 top
E17-9  [1,6/0,8]  233.68,91.44 0 top
E17-10  [1,6/0,8]  233.68,88.27 0 top
E17-11  [1,6/0,8]  233.68,85.09 0 top
E17-12  [1,6/0,8]  233.68,81.92 0 top
E17-13  [1,6/0,8]  258.44,81.92 180 top
E17-14  [1,6/0,8]  258.44,85.09 180 top
E17-15  [1,6/0,8]  258.44,88.27 180 top
E17-16  [1,6/0,8]  258.44,91.44 180 top
E17-17  [1,6/0,8]  258.44,94.62 180 top
E17-18  [1,6/0,8]  258.44,97.79 180 top
E17-19  [1,6/0,8]  258.44,100.97 180 top
E17-20  [1,6/0,8]  258.44,104.14 180 top
E17-21  [1,6/0,8]  258.44,107.32 180 top
E17-22  [1,6/0,8]  258.44,110.49 180 top
E17-23  [1,6/0,8]  258.44,113.67 180 top
E17-24  [1,6/0,8]  258.44,116.84 180 top
E18  [DIL16]  246.38,138.43 270 top
E18-1  [1,6/0,8]  233.68,154.94 0 top
E18-2  [1,6/0,8]  233.68,151.77 0 top
E18-3  [1,6/0,8]  233.68,148.59 0 top
E18-4  [1,6/0,8]  233.68,145.42 0 top
E18-5  [1,6/0,8]  233.68,142.24 0 top
E18-6  [1,6/0,8]  233.68,139.07 0 top
E18-7  [1,6/0,8]  233.68,135.89 0 top
E18-8  [1,6/0,8]  233.68,132.72 0 top
E18-9  [1,6/0,8]  233.68,129.54 0 top
E18-10  [1,6/0,8]  233.68,126.37 0 top
E18-11  [1,6/0,8]  233.68,123.19 0 top
E18-12  [1,6/0,8]  233.68,120.02 0 top
E18-13  [1,6/0,8]  258.44,120.02 180 top
E18-14  [1,6/0,8]  258.44,123.19 180 top
E18-15  [1,6/0,8]  258.44,126.37 180 top
E18-16  [1,6/0,8]  258.44,129.54 180 top
E18-17  [1,6/0,8]  258.44,132.72 180 top
E18-18  [1,6/0,8]  258.44,135.89 180 top
E18-19  [1,6/0,8]  258.44,139.07 180 top
E18-20  [1,6/0,8]  258.44,142.24 180 top
E18-21  [1,6/0,8]  258.44,145.42 180 top
E18-22  [1,6/0,8]  258.44,148.59 180 top
E18-23  [1,6/0,8]  258.44,151.77 180 top
E18-24  [1,6/0,8]  258.44,154.94 180 top
E19  [DIL16]  246.38,168.91 270 top
E19-1  [1,6/0,8]  233.68,193.04 0 top
E19-2  [1,6/0,8]  233.68,189.87 0 top
E19-3  [1,6/0,8]  233.68,186.69 0 top
E19-4  [1,6/0,8]  233.68,183.52 0 top
E19-5  [1,6/0,8]  233.68,180.34 0 top
E19-6  [1,6/0,8]  233.68,177.17 0 top
E19-7  [1,6/0,8]  233.68,173.99 0 top
E19-8  [1,6/0,8]  233.68,170.82 0 top
E19-9  [1,6/0,8]  233.68,167.64 0 top
E19-10  [1,6/0,8]  233.68,164.47 0 top
E19-11  [1,6/0,8]  233.68,161.29 0 top
E19-12  [1,6/0,8]  233.68,158.12 0 top
E19-13  [1,6/0,8]  258.44,158.12 180 top
E19-14  [1,6/0,8]  258.44,161.29 180 top
E19-15  [1,6/0,8]  258.44,164.47 180 top
E19-16  [1,6/0,8]  258.44,167.64 180 top
E19-17  [1,6/0,8]  258.44,170.82 180 top
E19-18  [1,6/0,8]  258.44,173.99 180 top
E19-19  [1,6/0,8]  258.44,177.17 180 top
E19-20  [1,6/0,8]  258.44,180.34 180 top
E19-21  [1,6/0,8]  258.44,183.52 180 top
E19-22  [1,6/0,8]  258.44,186.69 180 top
E19-23  [1,6/0,8]  258.44,189.87 180 top
E19-24  [1,6/0,8]  258.44,193.04 180 top
E20  [DIL16]  217.17,113.03 270 top
E21  [DIL16]  217.17,151.13 270 top
E22  [DIL16]  214.63,184.15 180 top
E23  [DIL16]  191.77,113.03 270 top
E24  [DIL16]  191.77,151.13 270 top
E25  [DIL16]  166.37,113.03 270 top
E26  [DIL16]  166.37,151.13 270 top
E27  [DIL16]  140.97,113.03 270 top
E28  [DIL16]  140.97,151.13 270 top
E29  [DIL16]  115.57,113.03 270 top
E30  [DIL16]  115.57,151.13 270 top
E31  [DIL16]  90.17,113.03 270 top
E32  [DIL16]  90.17,151.13 270 top
E33  [DIL16]  64.77,113.03 270 top
E34  [DIL16]  64.77,151.13 270 top
E35  [DIL16]  39.37,113.03 270 top
E36  [DIL16]  13.97,113.03 270 top
F  [EDGE-CON2]  133.35,214.63 270 top
FA1  [2,54/0,8]  136.53,190.5 90 top
FA2  [2,54/0,8]  136.53,184.15 90 top
FB1  [2,54/0,8]  139.7,193.68 90 top
FB2  [2,54/0,8]  139.7,187.33 90 top
FC1  [2,54/0,8]  142.88,190.5 90 top
FC2  [2,54/0,8]  142.88,184.15 90 top
FD1  [2,54/0,8]  146.05,193.68 90 top
FD2  [2,54/0,8]  146.05,187.33 90 top
FE1  [2,54/0,8]  149.22,190.5 90 top
FE2  [2,54/0,8]  149.22,184.15 90 top
FF1  [2,54/0,8]  152.4,193.68 90 top
FF2  [2,54/0,8]  152.4,187.33 90 top
FH1  [2,54/0,8]  155.57,190.5 90 top
FH2  [2,54/0,8]  155.57,184.15 90 top
FJ1  [2,54/0,8]  158.75,193.68 90 top
FJ2  [2,54/0,8]  158.75,187.33 90 top
FK1  [2,54/0,8]  161.93,190.5 90 top
FK2  [2,54/0,8]  161.93,184.15 90 top
FL1  [2,54/0,8]  165.1,193.68 90 top
FL2  [2,54/0,8]  165.1,187.33 90 top
FM1  [2,54/0,8]  168.28,190.5 90 top
FM2  [2,54/0,8]  168.28,184.15 90 top
FN1  [2,54/0,8]  171.45,193.68 90 top
FN2  [2,54/0,8]  171.45,187.33 90 top
FP1  [2,54/0,8]  174.62,190.5 90 top
FP2  [2,54/0,8]  174.62,184.15 90 top
FR1  [2,54/0,8]  177.8,193.68 90 top
FR2  [2,54/0,8]  177.8,187.33 90 top
FS1  [2,54/0,8]  180.97,190.5 90 top
FS2  [2,54/0,8]  180.97,184.15 90 top
FT1  [2,54/0,8]  184.15,193.68 90 top
FT2  [2,54/0,8]  184.15,187.33 90 top
FU1  [2,54/0,8]  187.32,190.5 90 top
FU2  [2,54/0,8]  187.32,184.15 90 top
FV1  [2,54/0,8]  190.5,193.68 0 top
FV2  [2,54/0,8]  190.5,187.33 90 top
H  [EDGE-CON2]  69.85,214.63 270 top
HA1  [2,54/0,8]  73.03,190.5 90 top
HA2  [2,54/0,8]  73.03,184.15 90 top
HB1  [2,54/0,8]  76.2,193.68 90 top
HB2  [2,54/0,8]  76.2,187.33 90 top
HC1  [2,54/0,8]  79.38,190.5 90 top
HC2  [2,54/0,8]  79.38,184.15 90 top
HD1  [2,54/0,8]  82.55,193.68 90 top
HD2  [2,54/0,8]  82.55,187.33 90 top
HE1  [2,54/0,8]  85.72,190.5 90 top
HE2  [2,54/0,8]  85.72,184.15 90 top
HF1  [2,54/0,8]  88.9,193.68 90 top
HF2  [2,54/0,8]  88.9,187.33 90 top
HH1  [2,54/0,8]  92.08,190.5 90 top
HH2  [2,54/0,8]  92.08,184.15 90 top
HJ1  [2,54/0,8]  95.25,193.68 90 top
HJ2  [2,54/0,8]  95.25,187.33 90 top
HK1  [2,54/0,8]  98.42,190.5 90 top
HK2  [2,54/0,8]  98.42,184.15 90 top
HL1  [2,54/0,8]  101.6,193.68 90 top
HL2  [2,54/0,8]  101.6,187.33 90 top
HM1  [2,54/0,8]  104.78,190.5 90 top
HM2  [2,54/0,8]  104.78,184.15 90 top
HN1  [2,54/0,8]  107.95,193.68 90 top
HN2  [2,54/0,8]  107.95,187.33 90 top
HP1  [2,54/0,8]  111.12,190.5 90 top
HP2  [2,54/0,8]  111.12,184.15 90 top
HR1  [2,54/0,8]  114.3,193.68 90 top
HR2  [2,54/0,8]  114.3,187.33 90 top
HS1  [2,54/0,8]  117.47,190.5 90 top
HS2  [2,54/0,8]  117.47,184.15 90 top
HT1  [2,54/0,8]  120.65,193.68 90 top
HT2  [2,54/0,8]  120.65,187.33 90 top
HU1  [2,54/0,8]  123.83,190.5 90 top
HU2  [2,54/0,8]  123.83,184.15 90 top
HV1  [2,54/0,8]  127,193.68 90 top
HV2  [2,54/0,8]  127,187.33 90 top
J1  [DEC40PINH]  26.67,166.37 90 top
J1BB  [2,54/0,8]  38.1,161.29 0 top
J1BB1  [2,54/0,8]  45.72,161.29 0 top
J1D  [2,54/0,8]  38.1,199.39 0 top
J1D1  [2,54/0,8]  45.72,199.39 0 top
J1DD  [2,54/0,8]  38.1,157.48 0 top
J1DD1  [2,54/0,8]  45.72,157.48 0 top
J1F  [2,54/0,8]  38.1,195.58 0 top
J1F1  [2,54/0,8]  45.72,195.58 0 top
J1FF  [2,54/0,8]  38.1,153.67 0 top
J1FF1  [2,54/0,8]  45.72,153.67 0 top
J1J  [2,54/0,8]  38.1,191.77 0 top
J1J1  [2,54/0,8]  45.72,191.77 0 top
J1JJ  [2,54/0,8]  38.1,149.86 0 top
J1JJ1  [2,54/0,8]  45.72,149.86 0 top
J1L  [2,54/0,8]  38.1,187.96 0 top
J1L1  [2,54/0,8]  45.72,187.96 0 top
J1LL  [2,54/0,8]  38.1,146.05 0 top
J1LL1  [2,54/0,8]  45.72,146.05 0 top
J1N  [2,54/0,8]  38.1,184.15 0 top
J1N1  [2,54/0,8]  45.72,184.15 0 top
J1NN  [2,54/0,8]  38.1,142.24 0 top
J1NN1  [2,54/0,8]  45.72,142.24 0 top
J1R  [2,54/0,8]  38.1,180.34 0 top
J1R1  [2,54/0,8]  45.72,180.34 0 top
J1RR  [2,54/0,8]  38.1,138.43 0 top
J1RR1  [2,54/0,8]  45.72,138.43 0 top
J1T  [2,54/0,8]  38.1,176.53 0 top
J1T1  [2,54/0,8]  45.72,176.53 0 top
J1TT  [2,54/0,8]  38.1,134.62 0 top
J1TT1  [2,54/0,8]  45.72,134.62 0 top
J1V  [2,54/0,8]  38.1,172.72 0 top
J1V1  [2,54/0,8]  45.72,172.72 0 top
J1X  [2,54/0,8]  38.1,168.91 0 top
J1X1  [2,54/0,8]  45.72,168.91 0 top
J1Z  [2,54/0,8]  38.1,165.1 0 top
J1Z1  [2,54/0,8]  45.72,165.1 0 top
R1  2.2K  [0207/10]  132.08,76.2 270 top
R2  2.2K  [0207/10]  182.88,76.2 270 top
R3  2.2K  [0207/10]  175.26,71.12 270 top
R4  2.2K  [0207/10]  223.52,76.2 270 top
R5  390  [0207/10]  91.44,76.2 90 top
R6  750  [0207/10]  86.36,76.2 270 top
R7  390  [0207/10]  93.98,76.2 90 top
R8  750  [0207/10]  88.9,76.2 270 top
SV1  [MA12-1]  238.76,102.87 270 top
SV2  [MA12-1]  254,102.87 270 top
SV3  [MA12-1]  238.76,133.35 270 top
SV4  [MA12-1]  254,133.35 270 top
SV5  [MA12-1]  238.76,163.83 270 top
SV6  [MA12-1]  254,163.83 270 top
SV7  [MA08-1]  254,77.47 270 top
SV8  [MA08-1]  238.76,77.47 270 top
SV9  1-8  [MA08-1]  13.97,43.18 0 top
SV10  9-16  [MA08-1]  13.97,50.8 0 top
SV11  19-26  [MA08-1]  39.37,88.9 0 top
SV12  31-39  [MA09-1]  111.76,88.9 0 top
SV13  41-47  [MA07-1]  139.7,88.9 0 top
SV14  48-54  [MA07-1]  165.1,88.9 0 top
SV15  55-61  [MA07-1]  190.5,88.9 0 top
SV16  62-68  [MA07-1]  215.9,88.9 0 top
U$2  [EDGE-CON8]  0,0 0 top
U$6  [2,8]  5.71,209.55 0 top
U$7  [2,8]  56.52,209.55 0 top
U$8  [2,8]  259.71,209.55 0 top
U$9  [2,8]  208.91,209.55 0 top

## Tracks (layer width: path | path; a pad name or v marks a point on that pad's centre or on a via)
#31_INT_ENABLE  (via drill 0.61)
  Top 0.381: v101.6,44.45 101.6,87.63 SV12.1
  Bottom 0.381: v101.6,44.45 104.14,41.91 116.84,41.91 118.11,40.64 E7.8
#32_RQST  (via drill 0.61)
  Top 0.381: v123.19,82.55 123.19,52.07 120.02,48.9 E7.11
  Bottom 0.381: E7.9 120.65,43.18 123.19,45.72 123.83,45.72 124.46,46.36 124.46,48.26 120.65,48.26 E7.11 | v123.19,82.55 120.65,85.09 106.68,85.09 104.14,87.63 SV12.2
#33_SKIP_IOT
  Top 0.381: E7.12 120.02,51.44 121.28,52.71 121.28,61.6 116.2,66.68 116.2,85.09 118.11,87 118.11,91.44 116.84,92.71 106.68,92.71 106.68,90.17 SV12.3
#35_C0B
  Top 0.381: E8.3 111.12,76.84 109.86,78.11 109.86,85.73 111.76,87.63 SV12.5
#36_C1A
  Top 0.381: E8.5 112.39,71.76 113.67,73.03 113.67,88.27 SV12.6
#37_C1B
  Top 0.381: E8.6 111.12,69.22 107.95,72.39 107.95,77.47 107.31,78.11 107.31,86.36 107.95,87 107.95,90.81 108.58,91.44 116.84,91.44 116.84,90.17 SV12.7
#38_C2A
  Top 0.381: E8.8 118.75,66.68 117.47,67.95 117.47,85.09 119.38,87 119.38,87.63 SV12.8
#39_C2B
  Top 0.381: E8.9 120.02,69.22 121.92,71.12 121.92,87.63 SV12.9
#41_RECH\  (via drill 0.61)
  Top 0.381: R1.1 132.08,81.92 132.08,87.63 SV13.1 | 160.66,69.22 160.66,67.95 161.93,66.68 E4.7 163.19,65.41 168.28,60.33 168.28,42.55 168.91,41.91 187.32,41.91 187.32,41.28 E1.7 | 160.66,69.22 161.93,70.49 E4.5 | v158.75,80.01 158.75,75.57 160.66,73.66 160.66,69.22
  Bottom 0.381: 190.5,43.18 193.04,45.72 194.31,45.72 E1.10 | 190.5,43.18 188.59,41.28 E1.7 | 190.5,43.18 188.59,45.09 E1.5 189.23,45.72 194.31,50.8 E1.12 | v158.75,80.01 133.99,80.01 132.72,81.28 R1.1
#42  (via drill 0.61)
  Top 0.381: v181.61,54.61 173.99,62.23 173.99,93.98 v172.72,95.25
  Bottom 0.381: v181.61,54.61 185.42,50.8 186.69,50.8 E1.3 | v172.72,95.25 165.74,95.25 162.56,98.43 142.24,98.43 139.06,95.25 135.25,95.25 130.81,90.81 130.81,86.36 133.35,86.36 134.62,87.63 SV13.2
#43  (via drill 0.61)
  Top 0.381: v179.71,60.96 176.53,64.14 v176.53,92.71
  Bottom 0.381: v179.71,60.96 185.42,60.96 189.87,56.52 189.87,55.25 188.59,53.98 E1.2 | v176.53,92.71 138.43,92.71 137.16,91.44 137.16,90.17 SV13.3
#44  (via drill 0.61)
  Top 0.381: v158.75,62.23 156.21,64.77 156.21,76.84 v147.96,85.09
  Bottom 0.381: v158.75,62.23 185.42,62.23 189.87,57.79 192.41,57.79 194.31,55.88 E1.14 | v147.96,85.09 146.69,86.36 140.97,86.36 139.7,87.63 SV13.4
#45  (via drill 0.61)
  Top 0.381: v155.57,63.5 154.94,64.14 154.94,75.57 153.03,77.47 146.69,77.47 146.69,83.19 142.24,87.63 SV13.5
  Bottom 0.381: v155.57,63.5 185.42,63.5 189.87,59.06 197.49,59.06 197.49,55.25 196.22,53.98 E1.13
#46  (via drill 0.61)
  Top 0.381: v152.4,78.74 144.78,86.36 144.78,87.63 SV13.6
  Bottom 0.381: v152.4,78.74 160.02,78.74 161.93,76.84 E4.3
#47
  Top 0.381: E4.2 161.93,79.38 153.03,88.27 147.96,88.27 SV13.7
#48  (via drill 0.61)
  Top 0.381: v165.1,85.09 168.91,81.28 E4.14
  Bottom 0.381: v165.1,85.09 163.83,86.36 158.75,86.36 157.48,87.63 SV14.1
#49
  Top 0.381: E4.13 168.91,78.74 160.02,87.63 SV14.2
#50  (via drill 0.61)
  Top 0.381: v53.34,94.62 v53.34,61.6 | v144.15,99.7 152.4,91.44 162.56,91.44 162.56,90.17 SV14.3
  Bottom 0.381: v53.34,61.6 53.34,55.25 55.24,53.34 57.15,53.34 59.69,50.8 E10.3 | v53.34,94.62 53.34,98.43 140.97,98.43 142.24,99.7 v144.15,99.7
#51  (via drill 0.61)
  Top 0.381: v57.15,64.77 57.78,65.41 57.78,90.81 71.12,104.14 v71.12,122.56 | v164.47,110.49 164.47,89.54 SV14.4
  Bottom 0.381: v57.15,64.77 55.88,63.5 54.61,63.5 54.61,55.25 55.24,54.61 58.42,54.61 59.69,53.34 E10.2 | v71.12,122.56 71.12,125.1 150.5,125.1 155.57,120.02 155.57,109.86 160.66,109.86 161.29,110.49 v164.47,110.49
#52  (via drill 0.61)
  Top 0.381: v97.16,53.34 97.79,53.98 97.79,90.17 106.05,98.43 127,98.43 v127,99.7 | v169.54,99.7 167.64,97.79 167.64,90.17 SV14.5
  Bottom 0.381: v97.16,53.34 95.89,52.07 85.09,52.07 81.28,55.88 69.85,55.88 E10.14 | v127,99.7 129.54,102.24 132.72,102.24 135.89,105.41 146.05,105.41 149.22,102.24 158.12,102.24 161.29,105.41 163.83,105.41 v169.54,99.7
#53  (via drill 0.61)
  Top 0.381: v71.75,54.61 71.75,92.08 76.2,96.52 v76.2,99.7 | v172.09,99.7 171.45,99.06 171.45,91.44 170.18,90.17 SV14.6
  Bottom 0.381: v71.75,54.61 71.12,54.61 69.85,53.34 E10.13 | v76.2,99.7 76.2,106.05 83.19,106.05 85.09,107.95 95.25,107.95 97.16,106.05 108.58,106.05 110.49,107.95 120.65,107.95 122.56,106.05 133.99,106.05 135.89,107.95 146.05,107.95 147.96,106.05 159.38,106.05 161.29,107.95 163.83,107.95 v172.09,99.7
#54_RECL\  (via drill 0.61)
  Top 0.381: v65.41,50.8 65.41,48.9 67.94,46.36 E10.10 | 172.09,74.3 172.09,73.03 170.81,71.76 E4.10 169.54,70.49 168.28,69.22 168.28,65.41 172.09,61.6 v172.09,54.61 | 172.09,74.3 170.81,75.57 E4.12 | 172.09,74.3 172.09,87 172.72,87.63 SV14.7
  Bottom 0.381: 64.14,42.55 67.31,45.72 E10.10 | 64.14,42.55 62.23,40.64 E10.7 | 64.14,42.55 61.59,45.09 E10.5 | 66.04,50.8 v65.41,50.8 | 66.04,50.8 67.31,50.8 E10.12 | R3.1 174.62,76.2 171.45,76.2 E4.12 | 66.04,50.8 66.04,57.15 154.31,57.15 156.84,54.61 v172.09,54.61
#55_ENBH
  Top 0.381: SV15.1 182.88,87.63 182.88,81.92 R2.1 | E6.2 137.79,78.11 139.06,76.84 139.06,73.03 137.79,71.76 E6.5 | E2.11 194.94,73.03 193.68,71.76 193.68,67.95 194.94,66.68 E2.8
  Bottom 0.381: R2.1 183.51,81.28 184.15,81.28 186.69,78.74 E2.2 189.23,78.74 190.5,77.47 201.93,77.47 201.93,73.03 201.29,72.39 198.12,72.39 196.85,73.66 E2.11 | 184.15,69.85 185.42,69.85 186.69,71.12 E2.5 | 184.15,69.85 139.7,69.85 138.43,71.12 E6.5 | 184.15,69.85 186.69,67.31 193.04,67.31 194.31,66.04 E2.8
#56
  Top 0.381: E2.3 187.32,76.84 185.42,78.74 185.42,87.63 SV15.2
#57  (via drill 0.61)
  Top 0.381: v193.04,73.66 191.13,75.57 191.13,79.38 189.87,80.65 189.87,85.73 187.96,87.63 SV15.3
  Bottom 0.381: v193.04,73.66 188.59,69.22 E2.6
#58  (via drill 0.61)
  Top 0.381: v191.77,81.28 191.13,81.92 191.13,88.27 SV15.4
  Bottom 0.381: v191.77,81.28 193.04,80.01 203.2,80.01 203.2,73.03 201.29,71.12 198.12,71.12 196.85,72.39 193.68,72.39 193.68,70.49 194.94,69.22 E2.9
#59
  Top 0.381: E2.12 194.94,76.84 193.04,78.74 193.04,87.63 SV15.5
#60  (via drill 0.61)
  Top 0.381: v135.25,83.82 135.25,78.11 136.53,76.84 E6.3
  Bottom 0.381: v135.25,83.82 138.43,87 138.43,91.44 194.31,91.44 195.58,90.17 SV15.6
#61  (via drill 0.61)
  Top 0.381: v133.35,90.81 133.35,72.39 136.53,69.22 E6.6
  Bottom 0.381: v133.35,90.81 136.53,93.98 194.31,93.98 198.12,90.17 SV15.7
#62  (via drill 0.61)
  Top 0.381: v145.41,63.5 145.41,65.41 E6.8 | v180.34,59.69 184.15,63.5 184.15,90.81 186.06,92.71 208.28,92.71 208.28,90.17 SV16.1
  Bottom 0.381: v145.41,63.5 153.03,63.5 156.84,59.69 v180.34,59.69
#63  (via drill 0.61)
  Top 0.381: v161.29,102.24 142.88,102.24 140.97,100.33 140.97,77.47 144.15,74.3 E6.11
  Bottom 0.381: v161.29,102.24 165.1,98.43 191.77,98.43 198.75,91.44 209.55,91.44 210.82,90.17 SV16.2
#64  (via drill 0.61)
  Top 0.381: v125.73,80.01 129.54,83.82 129.54,91.44 143.51,105.41 147.96,105.41 147.96,108.59 149.22,109.86 160.66,109.86 160.66,112.4 161.29,113.03 173.35,113.03 173.35,99.7 174.62,98.43 212.09,98.43 212.09,91.44 213.36,90.17 SV16.3
  Bottom 0.381: v125.73,80.01 97.79,80.01 95.25,77.47 63.5,77.47 62.23,78.74 E11.2
#65  (via drill 0.61)
  Top 0.381: v55.88,76.84 55.88,93.98 63.5,101.6 v63.5,104.78
  Bottom 0.381: v55.88,76.84 55.88,76.2 60.33,71.76 E11.5 | v63.5,104.78 63.5,132.08 205.74,132.08 219.07,118.75 219.07,90.81 219.71,90.81 219.71,86.36 217.17,86.36 215.9,87.63 SV16.4
#66  (via drill 0.61)
  Top 0.381: v78.11,66.04 79.38,67.31 v79.38,128.27
  Bottom 0.381: v78.11,66.04 69.85,66.04 E11.8 | v79.38,128.27 80.01,128.91 183.51,128.91 193.68,118.75 193.68,98.43 203.84,98.43 210.82,91.44 217.17,91.44 218.44,90.17 SV16.5
#67
  Top 0.381: E11.11 69.22,74.3 70.48,75.57 70.48,99.7 73.03,102.24 78.11,102.24 78.11,128.91 78.74,129.54 219.07,129.54 219.07,92.08 220.98,90.17 SV16.6
#68_ENBL  (via drill 0.61)
  Top 0.381: E6.9 145.41,69.22 146.69,70.49 146.69,74.3 145.41,75.57 E6.12 144.15,76.84 142.88,78.11 142.88,83.19 v143.51,83.82
  Bottom 0.381: 223.52,83.82 223.52,87.63 SV16.7 | 223.52,83.82 223.52,81.92 R4.1 | E11.6 62.23,68.58 67.31,68.58 E11.9 69.85,68.58 76.83,68.58 77.47,69.22 77.47,75.57 | E11.3 62.23,76.2 67.31,76.2 E11.12 69.22,75.57 77.47,75.57 | 77.47,75.57 94.61,75.57 96.52,77.47 142.24,77.47 143.51,76.2 E6.12 | 223.52,83.82 v143.51,83.82
$34_C0A  (via drill 0.61)
  Top 0.381: v108.58,78.74 108.58,86.36 109.22,87 109.22,87.63 SV12.4
  Bottom 0.381: v108.58,78.74 110.49,78.74 E8.2
+15V  (via drill 0.61)
  Top 0.381: v57.78,17.78 57.78,21.59 BUS104.1
  Bottom 0.381: v57.78,17.78 57.78,13.97 U$2.DA2
-15V  (via drill 0.61)
  Top 0.762: v53.98,19.05 53.98,24.77 BUS103.1
  Bottom 0.762: U$2.DB2 53.98,13.97 v53.98,19.05 67.94,19.05 69.22,20.32 78.74,20.32 80.01,19.05 125.73,19.05 | 125.73,19.05 125.73,20.32 181.61,20.32 182.88,19.05 | 125.73,19.05 125.73,13.97 U$2.CB2 | 182.88,19.05 187.96,13.97 U$2.BB2 | 182.88,19.05 201.29,19.05 202.56,20.32 257.18,20.32 257.18,13.97 U$2.AB2
BREAK_CYCLE\  (via drill 0.61)
  Top 0.381: v161.93,15.24 161.93,24.77 BUS43.1
  Bottom 0.381: v161.93,15.24 161.93,13.97 U$2.BL2
BRK_DATA_CONT\  (via drill 0.61)
  Top 0.381: v165.1,15.24 165.1,21.59 BUS44.1
  Bottom 0.381: v165.1,15.24 165.1,13.97 U$2.BK2
BRK_IN_PROG\  (via drill 0.61)
  Top 0.381: v177.8,15.24 177.8,21.59 BUS48.1
  Bottom 0.381: v177.8,15.24 177.8,13.97 U$2.BE2
BUS_STROBE\
  Top 0.381: BUS61.1 102.23,27.94 102.87,27.31 102.87,23.5 103.5,22.86 103.5,13.97 U$2.CK1
C0\  (via drill 0.61)
  Top 0.381: v112.39,83.82 112.39,81.92 E8.1 | v114.94,82.55 114.94,29.21 BUS65.1 114.94,27.94 114.94,25.4 116.2,24.13 116.2,13.97 U$2.CE1
  Bottom 0.381: v112.39,83.82 113.67,83.82 v114.94,82.55
C1\  (via drill 0.61)
  Top 0.381: v105.41,68.58 105.41,33.66 107.31,31.75 107.31,29.21 BUS63.1 | v109.86,23.5 109.86,13.97 U$2.CH1 | v113.03,24.13 v113.03,26.67
  Bottom 0.381: v105.41,68.58 110.49,73.66 E8.4 | v109.86,23.5 112.39,23.5 v113.03,24.13 | v113.03,26.67 111.76,27.94 108.58,27.94 BUS63.1
C2\  (via drill 0.61)
  Top 0.381: v104.14,66.04 104.14,32.39 BUS62.1 105.41,31.12 105.41,28.58 106.68,27.31 106.68,24.77 106.05,24.13 106.05,13.97 U$2.CJ1
  Bottom 0.381: v104.14,66.04 105.41,67.31 114.3,67.31 118.11,71.12 E8.10
CPMA_DISABLE\
  Top 0.381: BUS53.1 76.2,27.94 76.2,13.97 U$2.CU1
DATA0\  (via drill 0.61)
  Top 0.381: E2.1 188.59,80.65 189.87,79.38 189.87,50.17 188.59,48.9 E1.4 188.59,47.63 194.31,41.91 198.12,41.91 v198.12,42.55 | BUS19.1 219.07,24.77 219.07,13.97 U$2.AR1
  Bottom 0.381: 218.44,30.48 218.44,31.12 BUS5.1 | 218.44,30.48 218.44,26.04 BUS19.1 | v198.12,42.55 208.91,31.75 210.19,31.75 212.09,29.85 214.63,29.85 215.26,30.48 218.44,30.48
DATA1\  (via drill 0.61)
  Top 0.381: E2.4 187.32,73.03 186.06,71.76 186.06,45.09 187.32,43.82 E1.6 189.23,43.18 v199.39,33.02 | BUS4.1 215.9,27.94 215.9,13.97 U$2.AS1
  Bottom 0.381: v199.39,33.02 202.56,29.85 208.28,29.85 208.91,30.48 210.19,30.48 212.09,28.58 215.26,28.58 BUS4.1
DATA2\  (via drill 0.61)
  Top 0.381: v196.22,60.33 193.68,57.79 193.68,45.09 194.94,43.82 E1.9 | U$2.AU1 209.55,13.97 209.55,27.94 BUS2.1
  Bottom 0.381: E1.9 196.22,42.55 198.12,40.64 198.12,28.58 208.91,28.58 BUS2.1 | v196.22,60.33 201.93,60.33 201.93,66.68 201.29,67.31 200.66,67.31 196.85,71.12 E2.10
DATA3\
  Top 0.381: 197.49,48.26 205.74,48.26 205.74,32.39 BUS1.1 207.01,31.12 207.01,28.58 208.28,27.31 208.28,13.97 U$2.AV1 | 197.49,48.26 196.85,48.26 E1.11 | 197.49,48.26 197.49,76.84 196.22,78.11 E2.13
DATA4\  (via drill 0.61)
  Top 0.381: v140.34,76.2 140.34,76.84 139.7,77.47 139.7,78.74 137.79,80.65 E6.1 | v151.13,74.93 152.4,73.66 v152.4,71.12 151.13,69.85 151.13,62.23 147.96,59.06 147.96,33.02 148.59,32.39 BUS29.1 149.22,31.12 149.22,13.97 U$2.BR1
  Bottom 0.381: v152.4,71.12 158.75,71.12 161.29,73.66 E4.4 | v140.34,76.2 141.6,74.93 v151.13,74.93
DATA5\  (via drill 0.61)
  Top 0.381: v149.86,68.58 146.69,65.41 146.69,60.33 | 146.69,60.33 146.69,29.21 BUS28.1 146.05,27.94 146.05,13.97 U$2.BS1 | v140.34,73.66 142.88,71.12 142.88,64.14 146.69,60.33
  Bottom 0.381: v149.86,68.58 161.29,68.58 E4.6 | v140.34,73.66 138.43,73.66 E6.4
DATA6\  (via drill 0.61)
  Top 0.381: v140.97,71.12 141.6,70.49 v141.6,67.31 141.6,33.02 140.34,31.75 140.34,29.21 BUS26.1 139.7,27.94 139.7,13.97 U$2.BU1
  Bottom 0.381: v140.97,71.12 143.51,71.12 E6.10 | v141.6,67.31 167.64,67.31 168.91,68.58 E4.9
DATA7\  (via drill 0.61)
  Top 0.381: v160.02,76.2 161.29,74.93 169.54,74.93 169.54,74.3 E4.11 | BUS25.1 136.53,31.12 v136.53,23.5 136.53,19.69 137.16,19.05 137.16,13.97 U$2.BV1 | v153.67,74.93 153.67,32.39 150.5,29.21 v150.5,24.13
  Bottom 0.381: 153.67,76.2 v160.02,76.2 | 153.67,76.2 148.59,76.2 146.05,78.74 E6.13 | v153.67,74.93 153.67,76.2 | v150.5,24.13 149.86,23.5 v136.53,23.5
DATA8\  (via drill 0.61)
  Top 0.381: E10.4 61.59,48.9 62.87,50.17 62.87,79.38 61.59,80.65 E11.1 | BUS87.1 15.88,31.12 15.88,13.97 U$2.DR1 | v41.27,39.37 38.73,36.83 30.48,36.83 30.48,29.85 29.84,29.21 v29.84,25.4
  Bottom 0.381: v41.27,39.37 50.8,39.37 59.69,48.26 E10.4 | v29.84,25.4 24.77,25.4 19.05,31.12 16.51,31.12 BUS87.1
DATA9\  (via drill 0.61)
  Top 0.381: E11.4 60.33,73.03 59.05,71.76 59.05,45.09 60.33,43.82 E10.6 60.33,42.55 58.42,40.64 v58.42,31.12 | BUS86.1 12.7,27.94 v12.7,23.5 12.7,13.97 U$2.DS1 | v39.37,28.58 38.1,27.31 v38.1,26.04
  Bottom 0.381: v58.42,31.12 46.99,31.12 44.45,28.58 v39.37,28.58 | v38.1,26.04 35.56,23.5 v12.7,23.5
DATA10\  (via drill 0.61)
  Top 0.381: E11.10 69.22,70.49 70.48,69.22 70.48,45.09 69.22,43.82 E10.9 67.94,42.55 60.96,35.56 v60.96,33.02 | BUS84.1 6.35,27.94 v6.35,19.69 6.35,13.97 U$2.DU1 | v49.53,32.39 42.55,25.4 v42.55,20.96
  Bottom 0.381: v60.96,33.02 60.33,32.39 v49.53,32.39 | v42.55,20.96 41.27,19.69 v6.35,19.69
DATA11\  (via drill 0.61)
  Top 0.381: E10.11 67.94,48.9 66.67,50.17 66.67,76.84 67.94,78.11 E11.13 | BUS83.1 3.81,31.12 v3.81,18.42 3.81,13.97 U$2.DV1 | v50.8,38.1 52.7,36.2 52.7,26.67 48.9,22.86 v48.9,19.05
  Bottom 0.381: v50.8,38.1 59.69,46.99 66.04,46.99 67.31,48.26 E10.11 | v48.9,19.05 48.26,18.42 v3.81,18.42
GND  (via drill 0.61)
